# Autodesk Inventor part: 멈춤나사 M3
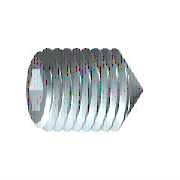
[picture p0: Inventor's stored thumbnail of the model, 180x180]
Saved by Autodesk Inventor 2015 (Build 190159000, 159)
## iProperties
IsCustomPart: 1
Created: 2012-02
Part Number: 멈춤나사 M3
Material: 강철, 연강
Description: 6각 소켓 머리 없는 멈춤 나사
Document SubType Name: Modeling
Standard: KS B 1028
Designer: test
Standards Organization: KS
Language: ko-KR
Size Designation: 원추점 M3x8
Categories: <MemberInstance><Categories><Category DisplayName="조임쇠" InternalName="e4da775c-781d-43d5-af7c-5136215cf5a6" Mnemonic="FSTN"><Category DisplayName="볼트" InternalN
Density: 1 g/cm^3
Appearance: 강철
Author: test
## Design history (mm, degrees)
sketch "스케치1"
  geometry: L1 (0, 0)-(5.5, 0); L2 (8, 0.866)-(8, 1.5); L3 (8, 1.5)-(0, 1.5); L4 (8, 0.866)-(6, 0.866); L5 (6, 0.866)-(5.5, 0); L6 (0, -0.3)-(0, 1.8) reference; L7 (0, 1.5)-(0, 0)
  constraints: 13 end point, 3 parallel, 1 collinear, 1 perpendicular, 1 point on line
  dimensions: "d0" = 2 distance of L2.start L4.end (= INTI); "d1" = 60 deg angle of L5 L1; "d2" = 3 diameter of L3 L1 (= NND); "d3" = 1.73205 diameter of L4 L1 (= 1.1547 x SW); "d5" = 8 distance from line of L2 L3.end (= NLG)
revolve "본체" sketch "스케치1" stored, may be unused: angle "d6" = 90 deg
sketch "스케치2"
  geometry: L1 (-0.433, 0.75)-(0.433, 0.75); L2 (0.433, 0.75)-(0.866, 0); L3 (0.866, 0)-(0.433, -0.75); L4 (0.433, -0.75)-(-0.433, -0.75); L5 (-0.433, -0.75)-(-0.866, 0); L6 (-0.866, 0)-(-0.433, 0.75); 3 further points
  constraints: 12 end point, 1 coincident, 1 horizontal, 13 other
extrude "슬롯" join sketch "스케치2" taper "d7" = 0 deg; stored distance "d21" = 10
workaxis "Work Axis1"
workplane "Work Plane1"
sketch "스케치4"
  geometry: L1 (0, 0.15)-(-1.35, 1.5) reference; L2 (0, -0.15)-(-1.35, -1.5) reference; L3 (-1.35, -1.5)-(0.15, 0); L4 (-1.35, 1.5)-(0.15, 0); 2 further points
  constraints: 4 end point, 1 coincident, 1 collinear, 1 horizontal alignment
body "Solid1"
feature "스레드" dims "d12" = 8 (= NLG), "d13" = 0
chamfer "모따기1" distance "d8" = 1.35 (computed from NND, SPD, FAWI); stored, may be unused: angle "d9" = 45 deg (= FAWI), second distance "d34" = 1.35 (computed from NND, SPD, FAWI)
chamfer "모따기2" distance "d10" = 0.30673 (= -0.5 x GD1 + 0.5 x NND); stored, may be unused: angle "d11" = 45 deg (= FAWI), second distance "d35" = 0.30673 (= -0.5 x GD1 + 0.5 x NND)
other parameters: "NND" = 3 [user parameter; used in 5 equation terms], "NLG" = 8 [user parameter; used in 2 equation terms], "INTI" = 2 [user parameter; used in 1 equation term], "FAWI" = 45 deg [user parameter; used in 4 equation terms], "SW" = 1.5 [user parameter; used in 2 equation terms], "GD1" = 2.38655 (= THREADDIA - 1.2269 x PTC) [user parameter; used in 2 equation terms], "d4" = 0, "FAWI1" = 45 deg [user parameter], "SPD" = 0.3 [user parameter; used in 2 equation terms], "d36" = 0, "d37" = 0, "GUL" = 0.30673 (= 0.61345 x PTC) [user parameter], "TOA" = 30 deg [user parameter], "THREADDIA" = 3 [user parameter; used in 1 equation term], "PTC" = 0.5 [user parameter; used in 4 equation terms], "GAL" = 0.30673 (= 0.61345 x PTC) [user parameter], "E0" = 1.7325 (= 1.155 x SW) [user parameter]
